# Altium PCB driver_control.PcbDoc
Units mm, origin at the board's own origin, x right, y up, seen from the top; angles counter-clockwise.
Board outline 95 x 62.6 mm, 2 copper layers (Top Layer, Bottom Layer); 60 components, 55 nets, 275 pads, 163 vias.
Unrouted connection lines stored in the file: 8.
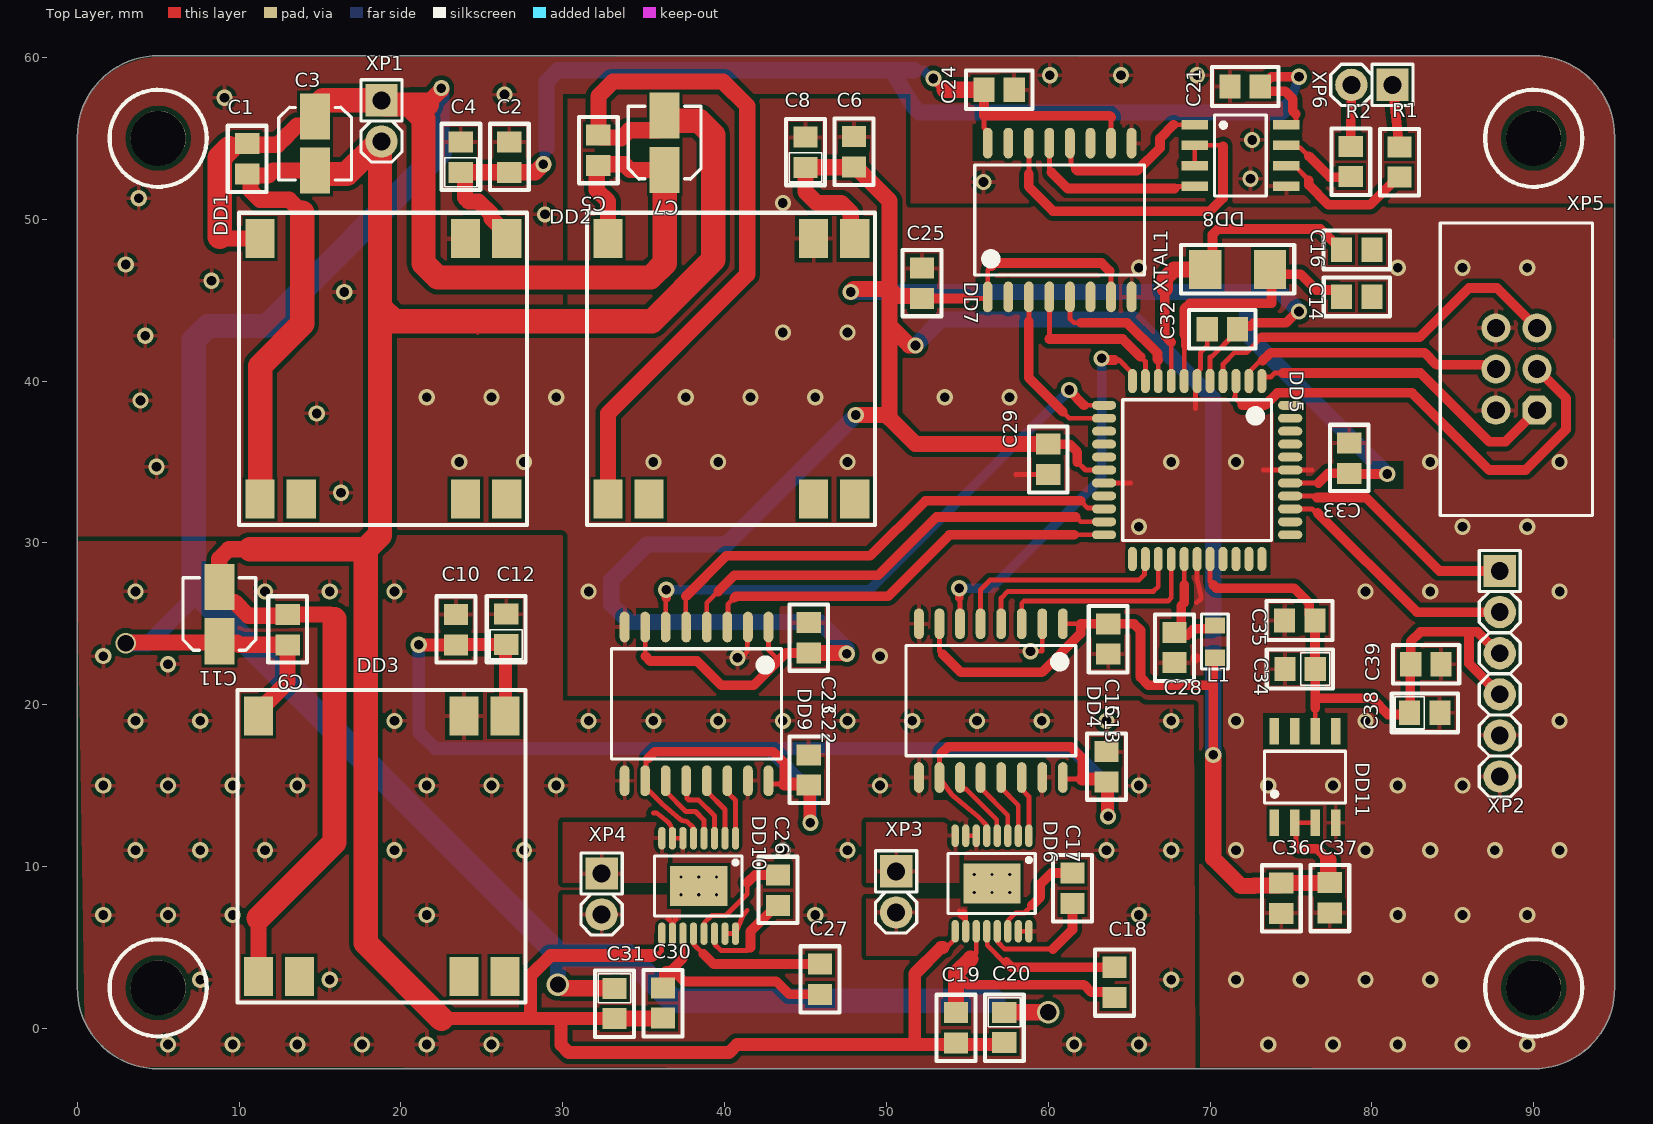
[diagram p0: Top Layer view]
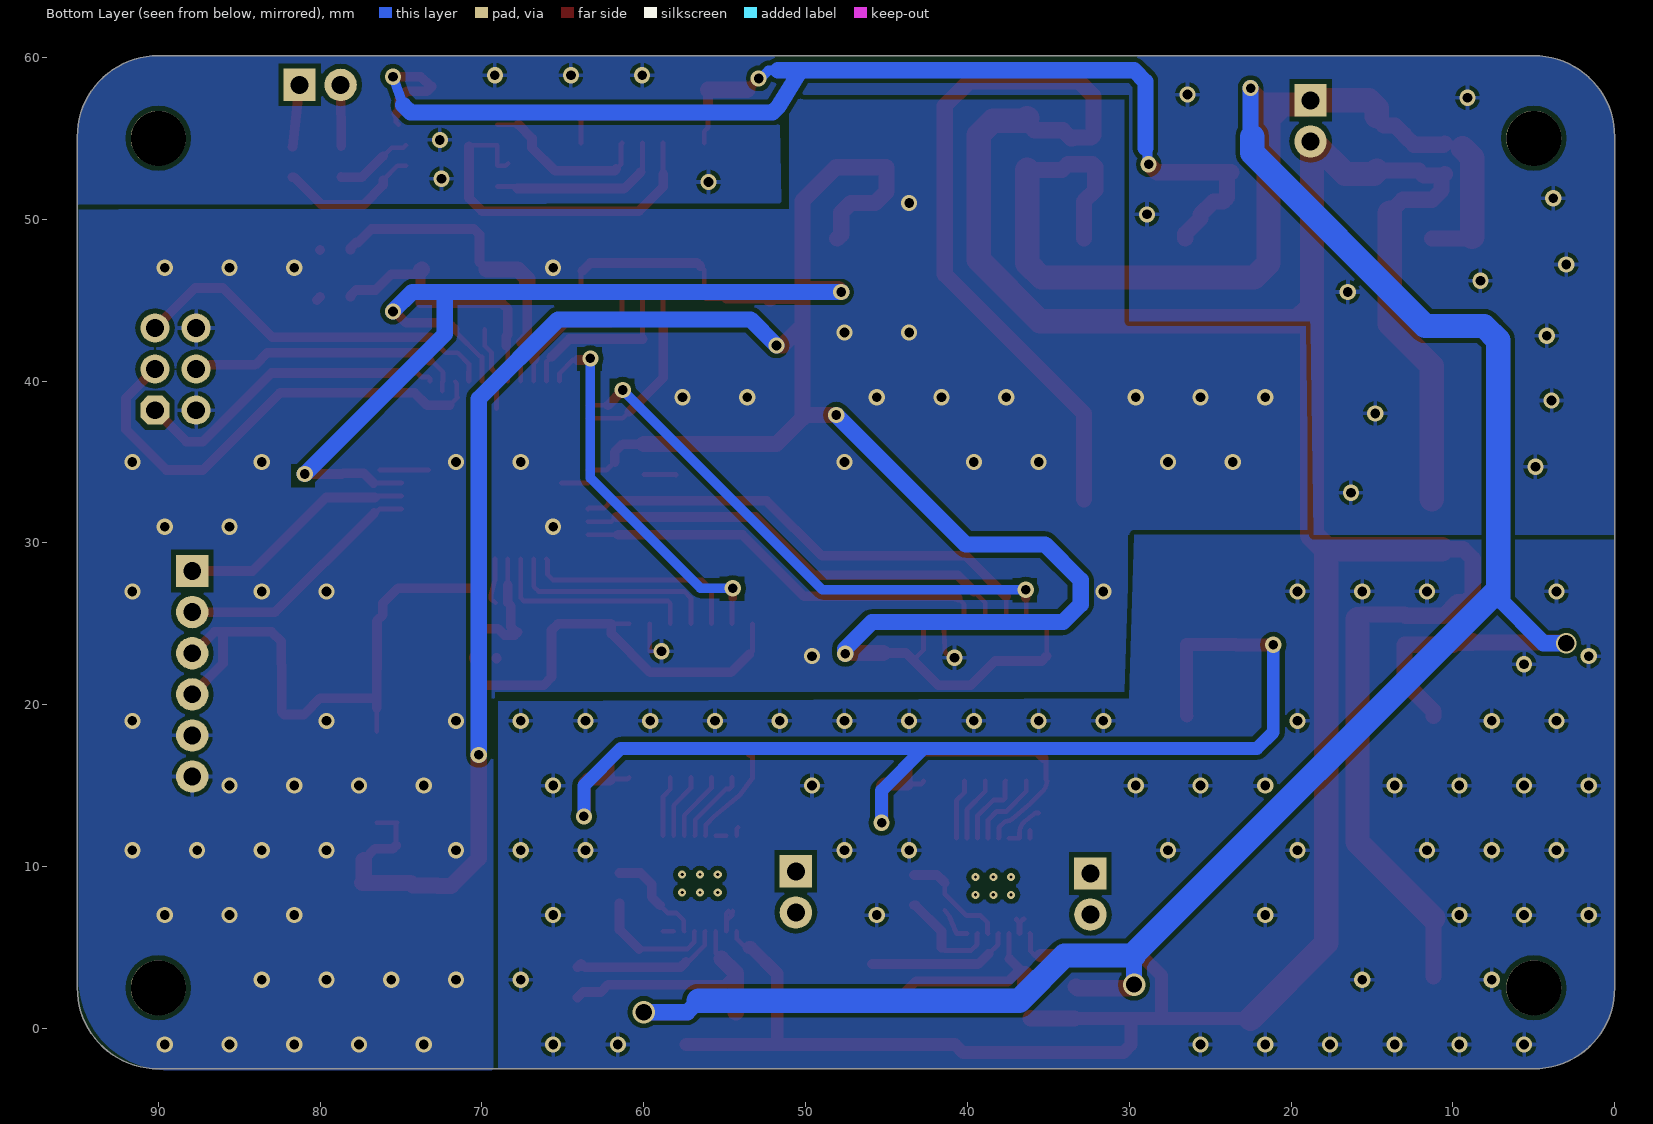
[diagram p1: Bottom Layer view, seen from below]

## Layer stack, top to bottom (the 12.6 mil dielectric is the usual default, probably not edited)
Top Solder: solder mask 0.0102, Solder Resist, Dk 3.5
Top Layer: signal copper 0.0356
Dielectric 1: dielectric 0.32, FR-4, Dk 4.8
Bottom Layer: signal copper 0.0356
Bottom Solder: solder mask 0.0102, Solder Resist, Dk 3.5

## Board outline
0,2.5 0,55.1 cw(c5,55.1) 5,60.1 4.9,60.1 89.9,60.1 90,60.1 cw(c90,55.1) 95,55.1 95,2.4 95,2.5 cw(c90,2.5) 90,-2.5 90.1,-2.5 5,-2.5 cw(c5,2.5)

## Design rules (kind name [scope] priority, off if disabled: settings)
Clearance [All] p1: gap=0.3 ignorepadtopadclearanceinfootprint=FALSE except(0.2: Arc-SMDPad Track-SMDPad SMDPad-SMDPad SMDPad-THPad SMDPad-Via SMDPad-Fill SMDPad-Poly SMDPad-Region SMDPad-Text SMDPad-Hole)
HoleSize [All] p1: absolutevalues=TRUE maxlimit=5 minlimit=0.5 maxpercent=80.000 minpercent=20.000
HoleToHoleClearance [All] p1: gap=0.3 allowstackedmicrovias=TRUE
PolygonConnect [All] p1: connectstyle=Relief reliefconductorwidth=0.254 reliefentries=4 polygonreliefangle="90 Angle" airgapwidth=0.254
RoutingVias [All] p1: holewidth=0.6 width=1 viastyle="Through Hole" minholewidth=0.6 minwidth=1 maxholewidth=0.6 maxwidth=1
ShortCircuit [All] p1: allowed=TRUE
SilkToSilkClearance [All] p1: silktosilkclearance=0.2
SilkToSolderMaskClearance [IsPad] p1: minsilkscreentomaskgap=0.2 clearancetoexposedcopper=TRUE
SolderMaskExpansion [All] p1: expansion=0.102 istentingtop=FALSE
Width [All] p1: maxlimit=4 minlimit=0.2 preferedwidth=0.3
25 further rules are at their usual default settings.

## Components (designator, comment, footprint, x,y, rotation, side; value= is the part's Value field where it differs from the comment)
C1 "0.1мкФ" Capacitor_0805 10.5,54.675 r270 top
C2 "0.1мкФ" Capacitor_0805 26.7,52.9 r90 top
C3 "100мкФ" CAPAE4643X46M 14.7,56.35 r270 top
C4 "10мкФ" Capacitor_tant_0805 23.7,52.9 r90 top
C5 "0.1мкФ" Capacitor_0805 32.2,53.325 r90 top
C6 "0.1мкФ" Capacitor_0805 48,53.225 r90 top
C7 "100мкФ" CAPAE4643X46M 36.3,53.05 r90 top
C8 "10мкФ" Capacitor_tant_0805 45,53.2 r90 top
C9 "0.1мкФ" Capacitor_0805 13,23.7 r90 top
C10 "0.1мкФ" Capacitor_0805 23.4,23.7 r90 top
C11 "100мкФ" CAPAE4643X46M 8.783,23.92 r90 top
C12 "10мкФ" Capacitor_tant_0805 26.5,23.725 r90 top
C13 "0.1мкФ" Capacitor_0805 63.6,15.225 r90 top
C14 "22пкФ" Capacitor_0805 78.125,45.2 r0 top
C15 "0.1мкФ" Capacitor_0805 63.7,25 r270 top
C16 "22пкФ" Capacitor_0805 78.118,48.11 r0 top
C17 "22пкФ" Capacitor_0805 61.5,9.6 r270 top
C18 "0.1мкФ" Capacitor_0805 64.1,3.775 r270 top
C19 "0.1мкФ" Capacitor_0805 54.3,0.975 r270 top
C20 "1мкФ" Capacitor_tant_0805 57.288,0.987 r270 top
C21 "0.1мкФ" Capacitor_0805 71.225,58.2 r0 top
C22 "0.1мкФ" Capacitor_0805 45.2,15.025 r90 top
C23 "0.1мкФ" Capacitor_0805 45.2,23.2 r90 top
C24 "0.1мкФ" Capacitor_0805 56.025,58 r0 top
C25 "0.1мкФ" Capacitor_0805 52.2,45.1 r90 top
C26 "22пкФ" Capacitor_0805 43.3,7.6 r90 top
C27 "0.1мкФ" Capacitor_0805 45.9,3.975 r270 top
C28 "0.1мкФ" Capacitor_0805 67.8,24.475 r270 top
C29 "0.1мкФ" Capacitor_0805 60,36.1 r270 top
C30 "0.1мкФ" Capacitor_0805 36.2,2.5 r270 top
C31 "1мкФ" Capacitor_tant_0805 33.2,2.475 r270 top
C32 "0.1мкФ" Capacitor_0805 71.7,43.2 r180 top
C33 "0.1мкФ" Capacitor_0805 78.6,34.3 r90 top
C34 "1мкФ" Capacitor_tant_0805 76.5,22.2 r180 top
C35 "0.1мкФ" Capacitor_0805 76.475,25.2 r180 top
C36 "10мкФ" Capacitor_0805 74.4,8.975 r270 top
C37 "0.1мкФ" Capacitor_0805 77.4,9 r270 top
C38 "1мкФ" Capacitor_tant_0805 82.325,19.5 r0 top
C39 "0.1мкФ" Capacitor_0805 82.4,22.5 r0 top
DD1 "TMR-1-2411SM" TMR1SM_SMD 11.3,32.7 r270 top
DD2 "TDR-2-2411SM" TMR1SM_SMD 32.8,32.7 r270 top
DD3 "TMR-1-2411SM" TMR1SM_SMD 11.2,3.2 r270 top
DD4 "ADuM1401" ADUM_SOIC 60.9,25 r270 top
DD5 "ATMEGA16-8UA" ATMEGA16-44A 73.2,40 r270 top
DD6 "DRV8874" DRV8874_TSOP127P600-8N 58.8,11.9 r270 top
DD7 "ADuM1301" ADUM_SOIC 56.26,45.2 r90 top
DD8 "ADM485" "SOIC_N8 (REF198, ADM485)" 69.05,55.84 r0 top
DD9 "ADuM1401" ADUM_SOIC 42.71,24.8 r270 top
DD10 "DRV8874" DRV8874_TSOP127P600-8N 40.675,11.75 r270 top
DD11 "REF198" "SOIC_N8 (REF198, ADM485)" 73.96,12.7 r90 top
L1 "Fixed inductor, 10мкГн, ±20%, 0805, 100mA, -55...+125°C" "IND: 0805" 70.3,23.9 r90 top value=10мкГн
R1 "120 Ом" resistor_0805 81.7,54.475 r270 top
R2 "120 Ом" resistor_0805 78.7,54.5 r270 top
XP1 "PLS-2" "CON: PLS-2" 18.796,56.074 r270 top
XP2 "Connector, 6pin, 2.54mm, 500VAC, 3A" "CON: PLS-6" 87.9,21.91 r270 top
XP3 "PLS-2" "CON: PLS-2" 50.6,8.43 r270 top
XP4 "PLS-2" "CON: PLS-2" 32.4,8.3 r270 top
XP5 "Connector, 6pin, 2.54mm, 500VAC, 3A" "CON: IDC-6MS" 88.93,40.74 r90 top
XP6 "PLS-2" "CON: PLS-2" 80,58.3 r180 top
XTAL1 "8Мгц" Z_0503 69.7,46.9 r0 top

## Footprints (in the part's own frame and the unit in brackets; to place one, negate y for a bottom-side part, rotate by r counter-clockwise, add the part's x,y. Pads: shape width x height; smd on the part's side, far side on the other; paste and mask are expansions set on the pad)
ADUM_SOIC [mm]
  oval 1.9x0.6 smd: 1(0,0) 2(0,-1.27) 3(0,-2.54) 4(0,-3.81) 5(0,-5.08) 6(0,-6.35) 7(0,-7.62) 8(0,-8.89) 9(9.5,-8.89) 10(9.5,-7.62) 11(9.5,-6.35) 12(9.5,-5.08) 13(9.5,-3.81) 14(9.5,-2.54) 15(9.5,-1.27) 16(9.5,0)
  silkscreen extent 1.35,-9.69 8.15,0.8
ATMEGA16-44A [mm]
  oval 1.5x0.55 smd: 1(0,0) 2(0,-0.8) 3(0,-1.6) 4(0,-2.4) 5(0,-3.2) 6(0,-4) 7(0,-4.8) 8(0,-5.6) 9(0,-6.4) 10(0,-7.2) 11(0,-8) 23(11,-8) 24(11,-7.2) 25(11,-6.4) 26(11,-5.6) 27(11,-4.8) 28(11,-4) 29(11,-3.2) 30(11,-2.4) 31(11,-1.6) 32(11,-0.8) 33(11,0)
  oval 0.55x1.5 smd: 12(1.5,-9.75) 13(2.3,-9.75) 14(3.1,-9.75) 15(3.9,-9.75) 16(4.7,-9.75) 17(5.5,-9.75) 18(6.3,-9.75) 19(7.1,-9.75) 20(7.9,-9.75) 21(8.7,-9.75) 22(9.5,-9.75) 34(9.5,1.75) 35(8.7,1.75) 36(7.9,1.75) 37(7.1,1.75) 38(6.3,1.75) 39(5.5,1.75) 40(4.7,1.75) 41(3.9,1.75) 42(3.1,1.75) 43(2.3,1.75) 44(1.5,1.75)
  silkscreen extent 1.15,-8.6 9.85,0.6, body extent 1.15,-8.6 9.85,0.6, height 1.2
Capacitor_0805 [mm]
  rect 1.3x1.5 smd: 1(0,0) 2(1.875,0)
  silkscreen extent -1.1,-1.2 3,1.2
Capacitor_tant_0805 [mm]
  rect 1.3x1.5 smd: 1(0,0) 2(1.875,0)
  silkscreen extent -1.1,-1.2 3,1.2
CAPAE4643X46M [mm] "Aluminum Electrolytic Capacitor, Body 4,30x4,30x4,60mm, IPC Low Density"
  rect 2.85x1.85 smd: 1(0,0) 2(3.35,0)
  silkscreen extent -0.57,-2.25 3.93,2.25
"CON: IDC-6MS" [mm] "IDC-6MS 6 pin PCB-mount connector"
  oct 1.8x1.8 hole 1.1: 1(-2.54,-1.27)
  round 1.8 hole 1.1: 2(-2.54,1.27) 3(0,-1.27) 4(0,1.27) 5(2.54,-1.27) 6(2.54,1.27)
  round 0.5 on Top Overlay: ""(-9.6,-4.5)
  round 0.5 on Mech1: ""(-8.4,-4)
  silkscreen extent -9.05,-4.7 9.03,4.7, body extent -8.89,-4.55 8.87,4.55, height 9
"CON: PLS-2" [mm]
  rect 2x2 hole 1.1: 1(-1.27,0)
  round 2 hole 1.1: 2(1.27,0)
  silkscreen extent -2.54,-1.27 2.54,1.27, body extent -2.57,-1.28 2.51,1.26, height 8.54
"CON: PLS-6" [mm]
  rect 2x2 hole 1.1: 1(-6.35,0)
  round 2 hole 1.1: 2(-3.81,0) 3(-1.27,0) 4(1.27,0) 5(3.81,0) 6(6.35,0)
  silkscreen extent -7.62,-1.27 7.62,1.27, body extent -7.62,-1.27 7.62,1.27, height 8.54
DRV8874_TSOP127P600-8N [mm]
  oval 1.4x0.45 smd: 1(0,0) 2(0,-0.65) 3(0,-1.3) 4(0,-1.95) 5(0,-2.6) 6(0,-3.25) 7(0,-3.9) 8(0,-4.55) 9(5.9,-4.55) 10(5.9,-3.9) 11(5.9,-3.25) 12(5.9,-2.6) 13(5.9,-1.95) 14(5.9,-1.3) 15(5.9,-0.65) 16(5.9,0)
  rect 2.46x3.55 smd: 17(2.95,-2.275)
  silkscreen extent 1.1,-5 4.8,0.4
"IND: 0805" [mm]
  rect 1x1.25 smd: 1(-1,0) 2(1,0)
  silkscreen extent -1.7,-0.82 1.7,0.82, body extent -1,-0.62 1,0.63, height 0.85
resistor_0805 [mm] "ЧИП-резистор типоразмера 0805"
  rect 1.3x1.5 smd: 0(0,0) 1(1.875,0)
  silkscreen extent -1.1,-1.2 3,1.2
"SOIC_N8 (REF198, ADM485)" [mm] "SOIC, 8-Leads, Body 4,90x3,90mm, Pitch 1,27mm, IPC Medium Density"
  rect 1.65x0.6 smd: 1(0,0) 2(0,-1.27) 3(0,-2.54) 4(0,-3.81) 5(5.65,-3.81) 6(5.65,-2.54) 7(5.65,-1.27) 8(5.65,0)
  silkscreen extent 1.22,-4.41 4.43,0.6
TMR1SM_SMD [mm]
  rect 2.4x1.8 smd: 1(0,0) 2(0,2.54) 6(0,12.7) 7(0,15.24) 8(-16.1,15.24) 9(-16.1,12.7) 14(-16.1,0)
  silkscreen extent -17.7,-1.3 1.6,16.5
Z_0503 [mm]
  rect 2x2.4 smd: 1(0,0) 2(4,0)
  silkscreen extent -1.5,-1.5 5.5,1.5

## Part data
C1 C2 C5 C6 C9 C10 C13 C14 C15 C16 C17 C18 C19 C21 C22 C23 C24 C25 C26 C27 C28 C29 C30 C32 C33 C35 C36 C37 C39: library part Capacity_0805
C3 C7 C11: library part Capacity_electrolity_polar_0805, "electrolity capacitor"
C4 C8 C12 C20 C31 C34 C38: library part Capacity_tantal_0805, "tanral capacitor"
DD5: library part ATMEGA16-44A
L1: library part Inductor_0805, Manufacturer="Murata Electronics", MaxCurrent=100mA, Package=0805, PartNumber=LQM21FN100M70L, Temperature=-55...+125°C, Tolerance=±20%, TypeInductor="Fixed inductor"
R1 R2: library part Resistor_0805
XP1 XP6: "https://www.chipdip.ru/product/wf-2r"
XP2: library part PLS-6, CurrentMax=3A, Manufacturer=Connfly, VoltageMax=500VAC
XP3 XP4: library part PLS-2-1
XP5: library part IDC-6, CurrentMax=3A, Manufacturer=Connfly, PartNumber=PLS-6, VoltageMax=500VAC
XTAL1: library part resonstor

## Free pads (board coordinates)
  round 3.4 hole 3.4 unplated: 5(5,55) 5(5,2.5) 5(90,2.5) 5(90,55)

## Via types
v1: diameter 1, hole 0.6, Top Layer to Bottom Layer, 148 vias
v2: diameter 0.5, hole 0.2, Top Layer to Bottom Layer, 12 vias
v3: diameter 1.4, hole 1, Top Layer to Bottom Layer, 2 vias
v4: diameter 1.27, hole 1, Top Layer to Bottom Layer, 1 vias

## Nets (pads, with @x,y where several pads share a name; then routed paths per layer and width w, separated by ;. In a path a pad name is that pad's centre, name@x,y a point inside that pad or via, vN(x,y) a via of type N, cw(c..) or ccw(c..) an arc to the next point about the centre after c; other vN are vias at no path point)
+5B: C6.1 C8.1 C15.1 C23.1 C25.1 C29.1 C32.1 C33.1 C36.1 C37.1 DD2.8 DD4.1 DD4.7 DD5.5 DD5.17 DD5.38 DD7.1 DD7.7 DD9.1 DD9.7 DD11.2 DD11.3 L1.1 | length 273
  Top Layer w0.3: DD9.7 35.1,24.79 35.1,23 ; DD9.1 42.71,23.39 43.35,22.75 ; DD4.7 53.28,23.32 53.5,23.1 ; 54.9,45.1 56.16,45.1 DD7.1 56.26,46.86 56.5,47.1 ; DD4.1 62,25 ; 61.8,35 62.3,34.5 DD5.17 ; 63.8,46.8 63.88,46.72 DD7.7 ; DD5.5 70,41.5 70.1,41.5 71.6,43 C32.1@71.6,43.3 ; DD5.38 76.7,33.7 ; 75.3,11.3 75.3,12.63 DD11.2 DD11.3
  Top Layer w0.6: 35.1,23 35.4,22.7 38.3,22.7 39.8,21.2 41.8,21.2 43.35,22.75 43.8,23.2 C23.1 ; C25.1 54.9,45.1 ; 53.5,23.1 54.6,22 59.6,22 62,24.4 62,25 C15.1 65.3,25 65.7,24.6 65.7,21.7 66.2,21.2 70.2,21.2 ; 56.5,47.1 56.7,47.3 63.3,47.3 63.8,46.8 ; C29.1 61.3,36.1 61.8,35.6 61.8,35 ; v1(70.2,16.9) 70.2,21.2 ; L1.1@70.2,22.9 70.2,21.2 ; C32.1 71.9,43.4 72.5,43.4 72.7,43.6 74.692,43.6 75.392,44.3 v1(75.5,44.3) ; 75.3,11.3 75.5,11.1 76.6,11.1 77.3,10.4 ; 76.7,33.7 77.3,34.3 C33.1 ; C33.1@78.65,34.25 v1(80.95,34.25)
  Top Layer w1: C23.1 47.5,23.2 v1(47.55,23.15) ; v1(47.8,45.5) 47.986,45.686 50.2,45.686 ; DD2.8 47.8,49.04 47.8,50.414 47.214,51 45.7,51 45,51.7 C8.1 45.012,53.212 47.987,53.212 C6.1 48.1,53.225 50.2,51.125 50.2,45.686 ; v1(48.1,37.9) 50,37.9 50.2,37.7 ; v1(51.8,42.2) 51.4,42.2 50.2,43.4 ; C25.1 52.05,45.25 50.636,45.25 50.2,45.686 ; C29.1 51.8,36.1 50.2,37.7 ; v1(70.2,16.9) 70.2,10.5 71.9,8.8 72.728,8.8 72.753,8.825 74.25,8.825 C36.1 74.413,8.988 77.388,8.988 C37.1 77.3,9.1 77.3,10.4 ; L1.1@70.2,22.9 L1.1 ; 50.2,37.7 50.2,43.4 ; 50.2,43.4 50.2,45.686
  Bottom Layer w1: v1(47.55,23.15) 47.55,23.45 45.9,25.1 34.1,25.1 33,26.2 33,27.7 35.2,29.9 40.1,29.9 v1(48.1,37.9) ; v1(47.8,45.5) 72.3,45.5 ; v1(51.8,42.2) 53.4,43.8 65.3,43.8 70.2,38.9 v1(70.2,16.9) ; v1(75.5,44.3) 74.3,45.5 72.3,45.5 ; v1(80.95,34.25) 72.3,42.9 72.3,45.5
+5B_DRV: C10.1 C12.1 C13.1 C22.1 DD3.8 DD4.10 DD4.16 DD6.5 DD9.10 DD9.16 DD10.5 | length 110.1
  Top Layer w0.3: 35.3,16.7 35.147,16.547 35.147,15.357 DD9.10 ccw(c36.032,15.3) 35.366,14.634 36.1,13.9 37.22,12.944 ccw(c37.61,13.4) 37.61,12.8 37.663,12.8 38.046,12.417 38.046,11.779 DD10.5 ; DD9.16 42.71,15.239 42.849,15.1 43.7,15.1 ; 53.4,17 53.28,16.88 DD4.10 ccw(c53.381,15.5) 53.31,15.429 cw(c53.097,15.217) 53.339,15.394 54.027,14.463 ccw(c54.55,14.85) 54.135,14.35 55.635,13.103 56.171,12.567 56.171,11.929 DD6.5 ; DD4.16 61,15.4 62.1,15.4
  Top Layer w0.6: 35.3,16.7 35.7,17.1 43,17.1 43.7,16.4 43.7,15.1 ; 53.4,17 53.8,17.4 61.4,17.4 62.1,16.7 62.1,15.4
  Top Layer w0.8: v1(21.1,23.7) C10.1 23.413,23.713 26.452,23.713 26.47,23.695 26.47,19.33 DD3.8 ; 43.7,15.1 45.125,15.1 C22.1 45.262,14.963 45.262,12.738 v1(45.3,12.7) ; 62.1,15.4 63.425,15.4 C13.1 63.662,15.163 63.662,13.136 v1(63.7,13.097)
  Bottom Layer w0.8: v1(21.1,23.7) 21.1,18.3 22.1,17.3 42.7,17.3 ; v1(45.3,12.7) 45.3,14.7 42.7,17.3 ; v1(63.7,13.097) 63.7,15 61.4,17.3 42.7,17.3
+5B_RS: C2.1 C4.1 C21.2 C24.1 DD1.8 DD7.10 DD7.16 DD8.8 | length 91.6
  Top Layer w0.3: 56.025,56.4 56.025,55.666 56.26,55.431 DD7.16 ; DD7.10 63.88,56.28 63.9,56.3 ; DD8.8@75.15,55.84 75.3,55.99 75.3,56.5
  Top Layer w0.6: v1@53.008,58.7 v1(52.9,58.7) 53.6,58 ; C24.1 56.025,56.4 63.8,56.4 63.9,56.3 ; 75.3,56.5 75.1,56.7 75.1,57.449 74.65,57.899 73.401,57.899 C21.2 73.8,58.8 v1(75.5,58.8)
  Top Layer w1: C4.1 C2.1 28.3,52.9 v1(28.8,53.4) ; C4.1@23.8,52.9 23.95,52.75 23.95,51.336 24.186,51.1 24.79,51.1 25.6,50.29 25.6,50.04 26.54,49.1 DD1.8 ; 53.6,58 C24.1
  Bottom Layer w0.6: v1(28.8,53.4) 28.877,53.477 28.877,54.277 29,54.4 ; 51.7,59.2 52.292,59.2 52.792,58.7 v1(52.9,58.7) ; 74.864,57.05 v1(75.5,58.8)
  Bottom Layer w1: 29,54.4 29,58.5 29.7,59.2 50.3,59.2 ; 51.7,59.2 50.3,59.2 ; 74.864,57.05 74.414,56.6 52.045,56.6 51.669,56.976 51.607,57.076 50.3,59.2
+5В: C14.2 C16.2 | length 0.3
  Top Layer w0.6: C16.2 C16.2@80.003,48.1 ; C14.2 C14.2@80.2,45
+27B: C1.1 C3.1 C5.1 C7.1 C9.1 C11.1 C18.2 C19.1 C20.1 C27.2 C30.1 C31.1 DD1.14 DD2.14 DD3.14 DD6.11 DD10.11 XP1.1 | length 224.9
  Top Layer w0.3: 37.4,4.3 37.425,4.325 DD10.11 ; 55.2,4.3 55.55,4.65 DD6.11
  Top Layer w0.6: 36.45,3.35 36.75,3.65 ; 37.4,4.3 36.75,3.65 ; C27.2 44,2.1 43.2,2.9 37.5,2.9 36.75,3.65 ; 54.3,3.4 55,2.7 62.2,2.7 62.65,2.25 63.75,2.25 C18.2
  Top Layer w1: v4(3,23.8) 3.052,23.852 8.714,23.852 C11.1 ; C11.1@8.783,23.823 9.877,23.823 10,23.7 C9.1 13,21.4 11.2,19.6 DD3.14 ; 8.8,48.9 8.9,48.8 DD1.14 ; 9.4,54.4 9.55,54.55 ; C1.1 10.575,54.6 12.4,54.6 13,55.2 13,55.214 13.586,55.8 14.275,55.8 14.7,56.225 C3.1 ; 21.594,57.094 v1@22.5,58 ; v3(29.7,2.7) 29.808,2.7 30.033,2.475 C31.1 ; DD2.14 32.8,51.1 32.1,51.8 32.1,53.225 C5.1 32.275,53.4 33.8,53.4 34.15,53.05 C7.1 ; C31.1@33.287,2.587 C31.1@33.3,2.575 ; C30.1 36.3,2.5 36.45,2.65 36.45,3.35 ; C19.1@54.3,1 C19.1@54.312,0.988 ; C19.1@54.3,1.4 54.3,3.4 55.2,4.3 ; C20.1 57.294,0.994 59.994,0.994 v3(60,1)
  Top Layer w1.5: 8.8,48.9 8.8,53.8 9.4,54.4 ; C3.1 14.7,56.85 15.194,57.344 XP1.1 19.046,57.094 20.521,57.094 ; 21.594,57.094 20.521,57.094 ; C7.1 36.3,47.279 35.421,46.4 22.279,46.4 21.4,47.279 21.4,56.216 20.521,57.094
  Bottom Layer w1: v4(3,23.8) 4.4,23.8 7.2,26.6 7.2,26.7 ; 22.4,55.1 22.5,55.2 v1(22.5,58.1) ; v3(29.7,2.7) 29.7,4.5 ; 56.6,1.7 57.3,1 v3(60,1)
  Bottom Layer w1.5: 7.2,26.7 7.2,27.1 ; 22.4,55.1 22.4,54.1 11.7,43.4 8.079,43.4 7.2,42.521 7.2,27.1 ; 56.6,1.7 36.8,1.7 34,4.5 29.7,4.5 29.7,4.6 7.2,27.1
AREF: C34.1 C35.1 C38.1 C39.1 DD5.29 DD11.6 XP2.3 XP2.4 | length 37.8
  Top Layer w0.3: DD5.29 70,27.6 70.2,27.4 ; DD11.6 76.5,19.8
  Top Layer w0.6: 70.2,27.4 70.4,27.2 75.2,27.2 76.125,26.275 76.125,25.55 C35.1 76.487,25.187 76.487,22.213 C34.1 76.5,20.4 ; 76.5,19.8 76.5,20.4 ; XP2.4 86,22.54 86,24.5 ; XP2.3 87.853,23.18 86.533,24.5 86,24.5 ; 76.5,20.4 80,20.4 81,19.4 82.225,19.4 C38.1 82.362,19.537 82.362,22.463 C39.1 82.4,23.9 83,24.5 86,24.5
DRV11: DD5.22 DD9.3 | length 26.4
  Top Layer w0.3: DD9.3 40.2,24.83 40.2,26.2 40.6,26.6 ; 61.6,30.5 DD5.22
  Top Layer w0.6: 40.6,26.6 40.7,26.7 50.1,26.7 53.9,30.5 61.6,30.5
DRV12: DD5.21 DD9.4 | length 28.4
  Top Layer w0.3: DD9.4 38.9,26.3 39.6,27 ; 61.7,31.6 62,31.3 DD5.21
  Top Layer w0.6: 39.6,27 40.6,28 49.5,28 53.1,31.6 61.7,31.6
DRV13: DD5.20 DD9.5 | length 30.4
  Top Layer w0.3: 37.6,26.7 37.6,24.83 DD9.5 ; 62,32.6 62.452,32.148 63.402,32.148 DD5.20
  Top Layer w0.6: 37.6,26.7 40.1,29.2 49,29.2 52.4,32.6 62,32.6
DRV14: DD5.12 DD9.6 | length 34.9
  Top Layer w0.3: DD9.6 36.36,26.56 v1@36.4,26.6 ; 62.213,38.5 DD5.12
  Top Layer w0.6: v1@36.4,26.6 v1(36.4,27.1) ; v1(61.3,39.45) 61.3,39.413 62.213,38.5
  Bottom Layer w0.6: v1(36.4,27.1) 48.95,27.1 v1(61.3,39.45)
DRV21: DD4.3 DD5.26 | length 13.6
  Top Layer w0.3: DD4.3 58.36,26.26 58.5,26.4 67.4,26.4 67.6,26.6 DD5.26 DD5.26@67.6,28.457
DRV22: DD4.4 DD5.25 | length 13.3
  Top Layer w0.3: DD4.4 57.09,26.59 57.5,27 66.5,27 66.8,27.3 DD5.25
DRV23: DD4.5 DD5.24 | length 13.6
  Top Layer w0.3: DD4.5 55.82,27.12 56.4,27.7 65.6,27.7 65.952,28.052 65.952,28.952 DD5.24
DRV24: DD4.6 DD5.11 | length 24
  Top Layer w0.3: 54.5,26.6 54.55,26.55 DD4.6 ; 64.1,41.3 64.375,41.3 65.2,40.475 DD5.11
  Top Layer w0.5: 54.5,26.6 v1(54.5,27.2)
  Top Layer w0.6: v1@63.3,41.3 64.1,41.3
  Bottom Layer w0.6: v1(54.5,27.2) 56.5,27.2 63.3,34 v1(63.3,41.4)
ENB: DD5.13 DD7.3 | length 10.7
  Top Layer w0.3: 58.8,43.7 DD7.3 ; 60.9,38.1 61.3,37.7 DD5.13
  Top Layer w0.6: 58.8,43.7 58.8,40.2 60.9,38.1
GND: C1.2 C3.2 C5.2 C7.2 C9.2 C11.2 C19.2 C20.2 C30.2 C31.2 DD1.1 DD2.1 DD3.1 DD6.9 DD10.9 XP1.2 | length 275.7
  Top Layer w0.3: 35.5,4.5 35.824,4.5 36.096,4.772 36.096,5.821 DD10.9 ; 53.5,5 53.725,5 54.25,5.525 DD6.9
  Top Layer w0.6: C30.2@36.1,0.625 C30.2
  Top Layer w0.8: 22.5,0.6 28,0.6 ; C31.2 29.9,0.6 ; 35.5,4.5 29.25,4.5 28,3.25 28,0.6 ; 53.5,5 53.375,5 51.75,3.375 51.75,-1 ; C20.2@57.4,-1 54.3,-1 51.75,-1 ; 28,0.6 29.9,0.6 ; 29.9,0.6 29.9,-1.031 30.369,-1.5 40.272,-1.5 40.772,-1 51.75,-1
  Top Layer w1: C1.2 10.6,52.7 C1.2@10.65,52.7 ; 10.679,29.6 9.363,29.6 8.777,29.014 8.777,27.276 C11.2 8.783,26.77 9.208,26.345 9.723,26.345 10.568,25.5 12.925,25.5 C9.2 15.625,25.575 15.9,25.3 ; DD3.1 11.2,6.8 ; 13.9,50.4 13.1,51.2 11.286,51.2 10.7,51.786 10.7,52.65 C1.2@10.65,52.7 ; C3.2 12.1,53 11.8,52.7 C1.2@10.65,52.7 ; DD2.1 32.8,38 41.4,46.6 41.4,57 39.9,58.5 33.1,58.5 32.2,57.6 C5.2 32.35,55.05 33.45,55.05 33.5,55 33.6,55 34.1,55.5 35.875,55.5 36.3,55.925 36.3,56.254 C7.2 ; C31.2@33.387,0.613 36.087,0.613 C30.2@36.1,0.625
  Top Layer w1.5: 10.679,29.6 17.821,29.6 ; 11.2,6.8 15.9,11.5 15.9,25.3 ; DD1.1 11.3,40.932 13.9,43.532 13.9,50.4 ; C3.2 14.7,52.975 14.875,52.8 16.656,52.8 18.66,54.804 XP1.2 18.7,54.709 18.7,44.579 ; 22.5,0.6 17.821,5.279 17.821,29.6 ; C7.2@36.3,56.254 36.475,56.079 38.421,56.079 39.3,55.2 39.3,47.489 35.511,43.7 19.579,43.7 18.7,44.579 ; 17.821,29.6 18.7,30.479 18.7,44.579
MISO: DD5.2 XP5.4 | length 17.4
  Top Layer w0.3: DD5.2@72.448,39.393 72.448,39.952 DD5.2 72.4,40.543 72.575,40.718 72.575,40.734 73.103,41.261 73.239,41.261 ; XP5.4@87.5,41 87.66,40.84 XP5.4
  Top Layer w0.6: 73.239,41.261 73.627,41.65 73.65,41.65 73.75,41.75 83.25,41.75 84,41 87.075,41 87.106,40.97 87.47,40.97 XP5.4@87.5,41
MOSI: DD5.1 XP5.1 | length 19.9
  Top Layer w0.3: DD5.1 73.2,40.135 73.315,40.25 73.75,40.25 74,40.5 74.5,40.5
  Top Layer w0.6: 74.5,40.5 82,40.5 82.001,40.499 82.499,40.499 82.501,40.501 82.999,40.501 87.25,36.25 88.25,36.25 XP5.1
NetC17_1: C17.1 DD6.14 | length 6.3
  Top Layer w0.3: DD6.14 57.529,6.029 57.529,6.667 57.995,7.133 58.533,7.133 59,7.6
  Top Layer w0.6: 59,7.6 59.5,8.1 59.5,8.9 60.2,9.6 C17.1
NetC17_2: C17.2 DD6.13 | length 7.6
  Top Layer w0.3: DD6.13 56.879,5.971 56.879,5.333 57.312,4.9 60.3,4.9
  Top Layer w0.6: 60.3,4.9 61.5,6.1 C17.2
NetC18_1: C18.1 DD6.12 | length 9.5
  Top Layer w0.3: DD6.12 56.229,5.971 56.229,5.135 57.263,4.1 57.4,4.1
  Top Layer w0.6: 57.4,4.1 57.725,3.775 63.65,3.775 63.875,4 C18.1
NetC26_1: C26.1 DD10.14 | length 6.5
  Top Layer w0.3: DD10.14 39.404,5.821 39.404,5.183 39.787,4.8 41.4,4.8 41.6,5
  Top Layer w0.6: 41.6,5 41.6,6 43.2,7.6 C26.1
NetC26_2: C26.2 DD10.13 | length 6.9
  Top Layer w0.3: DD10.13 38.754,5.879 38.754,6.517 39.208,6.971 40.071,6.971 41.4,8.3 41.4,9
  Top Layer w0.6: 41.4,9 41.875,9.475 C26.2
NetC27_1: C27.1 DD10.12 | length 9
  Top Layer w0.3: DD10.12 38.104,5.821 38.104,5.183 38.687,4.6 38.7,4.6
  Top Layer w0.6: 38.7,4.6 39.325,3.975 C27.1
NetC28_1: C28.1 DD5.27 L1.2 | length 7.6
  Top Layer w0.3: 68.4,27.4 DD5.27
  Top Layer w0.6: 68.4,27.4 68.4,26.8 68.403,26.797 68.403,26.3 68.225,26.122 68.225,24.825 67.875,24.475 C28.1 67.975,24.3 68.6,24.3 69,24.7 70.1,24.7 L1.2
NetDD4_11: DD4.11 DD6.4 | length 4.7
  Top Layer w0.3: DD4.11 54.55,14.931 54.689,14.793 54.907,14.793 56.821,12.879 56.821,11.929 DD6.4
NetDD4_12: DD4.12 DD6.3 | length 4.3
  Top Layer w0.3: DD4.12 55.82,14.85 57.5,13.17 DD6.3
NetDD4_13: DD4.13 DD6.2 | length 4
  Top Layer w0.3: DD4.13 57.09,14.85 58.15,13.79 DD6.2
NetDD4_14: DD4.14 DD6.1 | length 3.8
  Top Layer w0.3: DD4.14 58.36,14.769 58.8,14.329 DD6.1
NetDD6_8: DD6.8 XP3.1 | length 0.5
  Top Layer w0.3: DD6.8@54.181,12.404 54.25,12.334 DD6.8
NetDD6_10: DD6.10 XP3.2 | length 2.7
  Top Layer w0.3: 54.5,7.25 54.5,7.139 54.59,7.049 ; 54.539,6.999 54.871,6.667 54.871,6.029 DD6.10 54.9,7.1 54.75,7.25
NetDD7_12: DD7.12 DD8.1 | length 10.7
  Top Layer w0.3: DD7.12 61.397,54.643 61.397,53.403 61.7,53.1 ; 67.74,55.84 DD8.1
  Top Layer w0.6: 61.7,53.1 61.8,53 65.5,53 66.9,54.4 66.9,55 67.74,55.84
NetDD7_13: DD7.13 DD8.4 | length 11.2
  Top Layer w0.3: DD7.13 60.07,53.03 60.2,52.9 ; 67.8,51.9 67.93,52.03 DD8.4
  Top Layer w0.6: 60.2,52.9 61.2,51.9 67.8,51.9
NetDD7_14: DD7.14 DD8.2 DD8.3 | length 22.6
  Top Layer w0.3: 58.8,52.8 DD7.14 ; DD8.3@68.375,53.45 68.525,53.3 DD8.3 DD8.2 70.73,54.57 70.8,54.5
  Top Layer w0.6: 58.8,52.8 58.8,52 60.3,50.5 70,50.5 70.8,51.3 70.8,54.5
NetDD8_6: DD8.6 R1.1 | length 8.9
  Top Layer w0.3: DD8.6 75.225,53.3 76.1,52.425 76.1,52.4
  Top Layer w0.6: 76.1,52.4 76.1,52.1 77.3,50.9 79.9,50.9 81.6,52.6 R1.1
NetDD8_7: DD8.7 R2.1 | length 4.8
  Top Layer w0.3: DD8.7 74.85,54.42 75.58,54.42 76.104,53.896
  Top Layer w0.6: 76.104,53.896 77.401,52.599 78.674,52.599 R2.1
NetDD9_11: DD9.11 DD10.4 | length 4.9
  Top Layer w0.3: DD9.11 36.36,14.65 37.61,13.4 38.2,13.4 38.725,12.875 DD10.4
NetDD9_12: DD9.12 DD10.3 | length 4.6
  Top Layer w0.3: DD9.12 37.687,15.243 37.687,14.188 37.776,14.1 38.4,14.1 39.375,13.125 DD10.3
NetDD9_13: DD9.13 DD10.2 | length 4
  Top Layer w0.3: DD9.13 38.9,14.65 40.025,13.525 DD10.2
NetDD9_14: DD9.14 DD10.1 | length 3.8
  Top Layer w0.3: DD9.14 40.17,14.599 40.675,14.094 DD10.1
NetDD10_8: DD10.8 XP4.1 | length 0.5
  Top Layer w0.3: DD10.8 DD10.8@36.125,12.225
NetDD10_10: DD10.10 XP4.2 | length 2
  Top Layer w0.3: 36.511,6.752 36.538,6.726 36.571,6.726 36.746,6.55 36.746,5.879 DD10.10 36.804,5.879 36.804,6.517 36.962,6.675 36.962,6.776
NetR1_0: R1.0 XP6.1 | length 3.8
  Top Layer w0.6: XP6.1 R1.0
NetR2_0: R2.0 XP6.2 | length 3.8
  Top Layer w0.6: R2.0 XP6.2
POT1: DD5.37 XP2.1 | length 14.9
  Top Layer w0.3: DD5.37 76.512,32.9 76.612,32.8
  Top Layer w0.6: 76.612,32.8 79.636,32.8 84.176,28.26 XP2.1
POT2: DD5.36 XP2.2 | length 15.6
  Top Layer w0.3: DD5.36 76.3,32.1 76.5,31.9 76.6,31.9 76.652,31.848
  Top Layer w0.6: 76.652,31.848 82.78,25.72 XP2.2
RST: DD5.4 XP5.5 | length 24
  Top Layer w0.3: DD5.4@70.848,40.607 70.848,40.048 DD5.4 70.8,40.607 70.8,41.05 71.5,41.75 72.25,41.75 73.2,42.7
  Top Layer w0.6: 73.2,42.7 82.95,42.7 86,45.75 87.73,45.75 XP5.5
RXD: DD5.9 DD7.5 | length 9.4
  Top Layer w0.3: DD7.5 61.34,43.86 61.6,43.6 62,43.6 ; DD5.9 66.8,41.3
  Top Layer w0.6: 62,43.6 64.873,43.6 66.75,41.723 66.75,41.35 66.8,41.3
SCK: DD5.3 XP5.3 | length 29.5
  Top Layer w0.3: DD5.3@71.648,39.952 71.552,39.856 71.552,39.052 71.5,39 72,38.5
  Top Layer w0.6: 72,38.5 73.379,38.5 74.154,39.275 82.475,39.275 87.25,34.5 89.5,34.5 92,37 92,38.94 XP5.3
TXD: DD5.10 DD7.4 | length 10.3
  Top Layer w0.3: 60.07,42.6 DD7.4 ; 65.7,41.5 66,41.2 DD5.10
  Top Layer w0.6: 60.07,42.6 64.6,42.6 65.7,41.5
XT1: C14.1 DD5.7 XTAL1.2 | length 17.3
  Top Layer w0.3: DD5.7 68.4,42.1 68.5,42.2
  Top Layer w0.6: 68.5,42.2 68.5,42.773 68.4,42.873 68.4,44.449 68.751,44.8 73.8,44.8 73.8,46.8 74,46.6 75.6,46.6 76.575,45.625 77.775,45.625 78.125,45.275 C14.1
  Top Layer w1: XTAL1.2 XTAL1.2@73.8,46.8
XT2: C16.1 DD5.8 XTAL1.1 | length 20.3
  Top Layer w0.3: DD5.8 67.6,42.4
  Top Layer w0.6: 67.2,45.7 67.2,42.8 67.6,42.4 ; XTAL1.1 70.149,47.349 70.149,49.049 70.5,49.4 76.828,49.4 77.668,48.56 77.768,48.56 78.118,48.21 C16.1
  Top Layer w1: 67.2,45.7 67.2,46.314 67.786,46.9 XTAL1.1
Общ: C6.2 C8.2 C15.2 C23.2 C25.2 C28.2 C29.2 C32.2 C33.2 C34.2 C35.2 C36.2 C37.2 C38.2 C39.2 DD2.9 DD4.2 DD4.8 DD5.6 DD5.18 DD5.28 DD5.39 DD7.2 DD7.8 DD9.2 DD9.8 DD11.4 XP2.5 XP2.6 XP5.2 XP5.6 | length 19.7
  Top Layer w0.3: v1(40.8,22.9) 41.282,23.141 41.402,23.26 41.405,23.38 DD9.2 ; 58,34.2 58,34.225 C29.2 ; v1(58.9,23.3) 59.63,23.3 DD4.2 ; DD5.18 65.1,33.7 ; 69.1,38.3 69.1,40 DD5.6 69.2,40.543 69.4,40.743 69.4,41.251 69.4,41.749 69.825,42.174 C32.2 ; 69.153,26.3 69.316,26.424 69.446,26.554 69.446,26.716 69.437,26.751 69.2,27.7 DD5.28 ; 73.3,34.5 DD5.39 76.3,34.5
  Top Layer w0.6: C23.2@45.15,25.125 C23.2 ; 69.1,22.85 69.1,22.9 ; 78.6,34.3 78.65,34.25
  other v1: 73.6,-1 77.6,-1 81.6,-1 85.6,-1 89.6,-1 71.6,3 75.6,3 79.6,3 83.6,3 81.6,7 85.6,7 89.6,7 71.6,11 79.6,11 83.6,11 87.6,11 91.6,11 73.6,15 77.6,15 81.6,15 85.6,15 71.6,19 79.6,19 91.6,19 49.6,23 31.6,27 79.6,27 83.6,27 91.6,27 65.6,31 85.6,31 89.6,31 23.6,35 27.6,35 35.6,35 39.6,35 47.6,35 67.6,35 71.6,35 83.6,35 91.6,35 21.6,39 25.6,39 29.6,39 37.6,39 41.6,39 45.6,39 53.6,39 57.6,39 43.6,43 47.6,43 65.6,47 81.6,47 85.6,47 89.6,47 43.6,51
Общ_DRV: C10.2 C12.2 C13.2 C22.2 DD3.9 DD4.9 DD4.15 DD6.6 DD6.7 DD6.15 DD6.16 DD9.9 DD9.15 DD10.6 DD10.7 DD10.15 DD10.16 | length 6.4
  Top Layer w0.3: 35.6,13.3 35.8,13.3 35.882,13.236 36.5,12.75 cw(c35.836,12.086) 36.775,12.086 DD10.7 DD10.6 ; DD10.15 DD10.16 41.085,6.864 41.1,6.9 41.4,7.3 ; DD6.7 DD6.6 ; DD6.15 DD6.16
  other v1: 5.6,-1 9.6,-1 13.6,-1 17.6,-1 21.6,-1 25.6,-1 61.6,-1 65.6,-1 7.6,3 15.6,3 67.6,3 1.6,7 5.6,7 9.6,7 21.6,7 45.6,7 65.6,7 3.6,11 7.6,11 11.6,11 19.6,11 27.6,11 43.6,11 47.6,11 63.6,11 67.6,11 1.6,15 5.6,15 9.6,15 13.6,15 21.6,15 25.6,15 29.6,15 49.6,15 65.6,15 3.6,19 7.6,19 19.6,19 31.6,19 35.6,19 39.6,19 43.6,19 47.6,19 51.6,19 55.6,19 59.6,19 63.6,19 67.6,19 5.6,22.5 1.6,23 3.6,27 11.6,27 15.6,27 19.6,27
Общ_RS: C2.2 C4.2 C21.1 C24.2 DD1.9 DD7.9 DD7.15 DD8.5
  other v1: 16.3,33.1 4.9,34.7 14.8,38 3.9,38.8 4.2,42.8 16.5,45.5 8.3,46.2 3,47.2 28.9,50.3 3.8,51.3 56,52.3 72.5,52.5 72.6,54.9 9.1,57.5 26.4,57.7 60.1,58.9 64.5,58.9 69.2,58.9
pads on no net: DD1.2 DD1.6 DD1.7 DD2.2 DD2.6 DD2.7 DD3.2 DD3.6 DD3.7 DD5.14 DD5.15 DD5.16 DD5.19 DD5.23 DD5.30 DD5.31 DD5.32 DD5.33 DD5.34 DD5.35 DD5.40 DD5.41 DD5.42 DD5.43 DD5.44 DD6.17 DD7.6 DD7.11 DD10.17 DD11.1 DD11.5 DD11.7 DD11.8 XP5.
copper on no net:
  other v2: 37.3,8.25 38.4,8.25 39.5,8.25 55.425,8.4 56.525,8.4 57.625,8.4 37.3,9.35 38.4,9.35 39.5,9.35 55.425,9.5 56.525,9.5 57.625,9.5

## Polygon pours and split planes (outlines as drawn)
Общ on Top Layer "Общ_L01_P015" (solid, pour order 15): 19.4,30.5 30,30.5 30,20.25 68.739,20.25 69.09,19.9 69.09,-2.41 89.9,-2.5 ccw(c89.95,2.55) 95,2.5 94.9,51 51.3,51 51.3,57.75 30,57.75 30,42.9 19.4,42.9
no net on Top Layer "NONET_L01_P016" (solid, pour order 16): 24.7,42.9 24.8,42.9
Общ_DRV on Top Layer "Общ_DRV_L01_P011" (solid, pour order 11): 0,30.4 30,30.5 30,20.25 69,20.25 69.09,-2.5 3.905,-2.379 cw(c5.553,3.182) 0.452,0.424
Общ_RS on Top Layer "Общ_RS" (solid, pour order 8): 0,54.5 0,30.4 19.161,30.4 19,43.6 30,43.501 30,57.75 51.5,57.75 51.5,51 95,51 95,54.884 ccw(c90.033,55.099) 95.005,55.099 ccw(c89.999,55.099) 90.214,60.1 5,60 ccw(c5,55) 0,55
NetDD10_8 on Top Layer "NETDD10_8_L01_P004" (solid, remove dead copper, pour order 4): 36.5,12.75 36.5,9 30,9 30,12.75
NetDD6_8 on Top Layer "NETDD6_8_L01_P002" (solid, remove dead copper, pour order 2): 48.75,9 54.5,9 54.5,12.75 48.75,12.75
NetDD10_10 on Top Layer "NETDD10_10_L01_P003" (solid, remove dead copper, pour order 3): 30,8.25 37.3,8.25 37.3,4.8 37.25,4.75 37,5 30,5
NetDD6_10 on Top Layer "NETDD6_10_L01_P001" (solid, remove dead copper, pour order 1): 48.75,8 48.75,4.5 55,4.5 55,8
no net on Top Layer "NONET_L01_P000" (solid, pour order 0): 48,8.4
Общ on Bottom Layer "Общ_L02_P017" (solid, pour order 17): 19,43.6 19,30.5 30.1,30.5 30.1,20.8 69.2,20.8 69.2,-2.6 89.3,-2.6 ccw(c89.3,3) 94.9,3 94.9,50.6 51,50.6 51,57.7 30,57.7 30,43.7 18.8,43.7
Общ_DRV on Bottom Layer "Общ_DRV_L02_P014" (solid, pour order 14): 0,30.5 29.7,30.5 30,20.4 69,20.2 69,-2.5 5,-2.5 cw(c5,2.5) 0,2.5
Общ_RS on Bottom Layer "Общ_RS_L02_P012" (solid, pour order 12): 0,30.5 0,55.1 cw(c5,55.1) 5,60.1 89.5,60.1 cw(c89.95,55.05) 95,55.5 95,50.9 51.5,51 51.607,57.076 50.5,57.7 30,57.7 30,43.7 18.8,43.7 18.6,30.5

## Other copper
Top Layer:
  pour cut-out: 52.821,16.834 cw(c52.631,16.644) 52.9,16.644 52.9,14.1 59.1,14.1 59.1,16.8
  pour cut-out: 34.5,26 34.5,23.5 43.4,23.5 43.4,26
  pour cut-out: 46.886,47.346 49.194,47.346 49.194,50.2 46.886,50.2
  pour cut-out: 79.981,33.319 81.981,33.319 81.981,35.069 79.981,35.069
  pour cut-out: 44.181,22.319 46.181,22.319 46.181,24.069 44.181,24.069
  pour cut-out: 52.742,26.049 53.679,26.049 53.739,24.039 52.683,24.039
  pour cut-out: 68.072,56.34 68.034,51.335 70.21,51.273 70.313,56.339
  pour cut-out: 73.675,56.34 75.696,56.368 75.7,52.5 73.623,52.453
  pour cut-out: 55.5,44.1 55.501,46.401 64.339,46.377 64.306,44.1
  pour cut-out: 55.3,53.595 55.3,55.911 64.339,55.877 64.558,55.868 64.624,53.612
  pour cut-out: 57.988,55.661
  pour cut-out: 73.95,39.05 75.95,39.05 75.95,30 73.95,30
  pour cut-out: 62.45,38.75 64.45,38.75 64.45,30 62.45,30
  pour cut-out: 73.5,41 73.5,39 64.75,39 64.75,41
  pour cut-out: 73.75,30 73.75,28 64.75,28 64.75,30
  pour cut-out: 73.25,19.5 73.25,17.25 78.5,17.25 78.5,19.5
  pour cut-out: 76,15
  pour cut-out: 73.5,13.75 77,13.75 77,11.5 73.5,11.5
  pour cut-out: 69.5,23.625 69.5,22.25 71.25,22.25 71.25,23.625
  pour cut-out: 53.081,44.081 53.081,46.081 51.331,46.081 51.331,44.081
  pour cut-out: 70.781,42.381 70.781,44.381 69.031,44.381 69.031,42.381
  pour cut-out: 77.606,33.394 79.606,33.394 79.606,35.144 77.606,35.144
  pour cut-out: 58.981,33.344 60.981,33.344 60.981,35.094 58.981,35.094
  pour cut-out: 62.681,24.119 64.681,24.119 64.681,25.869 62.681,25.869
  pour cut-out: 81.5,23.5 81.5,21.5 83.25,21.5 83.25,23.5
  pour cut-out: 74.5,50.75
  pour cut-out: 30.25,41.75
Bottom Layer:
  pour cut-out: 53.8,27.9 55.307,27.9 55.307,26.421 53.8,26.421
  pour cut-out: 35.7,27.8 37.207,27.8 37.207,26.321 35.7,26.321
  pour cut-out: 80.3,34.9 81.807,34.9 81.807,33.421 80.3,33.421
  pour cut-out: 62.6,42.1 64.107,42.1 64.107,40.621 62.6,40.621
  pour cut-out: 60.6,40.15 62.107,40.15 62.107,38.671 60.6,38.671

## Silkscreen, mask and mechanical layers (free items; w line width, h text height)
Top Overlay:
  circle w0.254: c90,2.5 r3
  circle w0.254: c90,55 r3
  circle w0.254: c5,2.5 r3
  circle w0.254: c5,55 r3
Mechanical 1:
  lines w0.254: 4.9,60.1 89.9,60.1 ; 5,-2.5 cw(c5,2.5) 0,2.5 0,55.1 cw(c5,55.1) 5,60.1 ; 5.1,-2.5 90.1,-2.5 ; 90,-2.5 ccw(c90,2.5) 95,2.5 ; 90,60.1 cw(c90,55.1) 95,55.1 95,2.4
